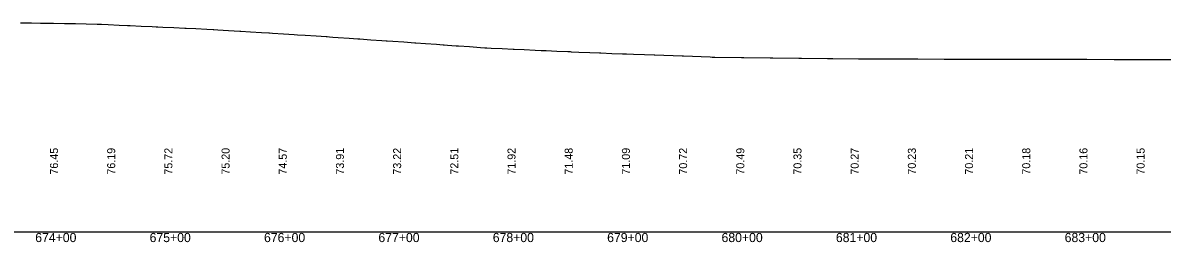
# Model space of a CAD drawing. Extents: x 2526761 to 2530854, y 882903 to 888012.
# Drawn here: x 2527707 to 2528703, y 887503 to 887695 of the extents above; entities that cross this region are included whole.
import ezdxf

# ---------------------------------------------------------------- set-up
doc = ezdxf.new("R2010")
doc.units = 0
for name, color, linetype in [('RD_DDB_Profile_EX', 7, 'Continuous'), ('RD_DDB_StaTX', 7, 'Continuous'), ('RD_DDB_StripGrade', 7, 'Continuous'), ('RD_GPK_Profile_Cell', 7, 'Continuous')]:
    doc.layers.add(name, color=color, linetype=linetype)

msp = doc.modelspace()

# ---------------------------------------------------------------- linework, layer by layer
at = {"layer": 'RD_DDB_Profile_EX'}
for points in [[(2527705.29, 887694.86), (2527714.86, 887694.71), (2527722.73, 887694.58), (2527724.43, 887694.55), (2527725.38, 887694.54), (2527734, 887694.4), (2527743.57, 887694.25), (2527747.73, 887694.18), (2527750.13, 887694.14), (2527753.14, 887694.09), (2527762.71, 887693.94), (2527772.28, 887693.78), (2527772.81, 887693.77), (2527773.7, 887693.73), (2527775.94, 887693.63), (2527781.85, 887693.36), (2527791.42, 887692.91), (2527798.7, 887692.57), (2527800.55, 887692.49), (2527800.99, 887692.47), (2527810.56, 887692.02), (2527820.13, 887691.57), (2527823.7, 887691.4), (2527825.27, 887691.33), (2527829.69, 887691.12), (2527839.26, 887690.67), (2527848.83, 887690.22), (2527850.1, 887690.16), (2527858.4, 887689.76), (2527867.97, 887689.31), (2527873.7, 887689.03), (2527874.21, 887689), (2527877.54, 887688.79), (2527887.11, 887688.19), (2527896.87, 887687.58), (2527897.77, 887687.52), (2527906.25, 887686.99), (2527915.82, 887686.38), (2527922.19, 887685.98), (2527922.71, 887685.94), (2527925.39, 887685.77), (2527934.96, 887685.16), (2527944.53, 887684.56), (2527947.38, 887684.38), (2527954.1, 887683.95), (2527963.67, 887683.34), (2527972.38, 887682.78), (2527973.24, 887682.72), (2527975.42, 887682.58), (2527978.15, 887682.39), (2527982.81, 887682.07), (2527992.38, 887681.41), (2528000.13, 887680.87), (2528000.61, 887680.83), (2528001.94, 887680.74), (2528011.51, 887680.08), (2528021.08, 887679.41), (2528024.92, 887679.15), (2528025.8, 887679.08), (2528030.65, 887678.75), (2528040.22, 887678.08), (2528049.79, 887677.42), (2528050.93, 887677.33), (2528059.36, 887676.75), (2528068.93, 887676.08), (2528074.71, 887675.68), (2528075.64, 887675.62), (2528078.5, 887675.4), (2528086.06, 887674.84), (2528087.51, 887674.74), (2528088.07, 887674.7), (2528097.64, 887673.98), (2528107.21, 887673.26), (2528111, 887672.98), (2528111.31, 887672.97), (2528112.98, 887672.85), (2528116.78, 887672.68), (2528126.35, 887672.26), (2528135.92, 887671.83), (2528136.34, 887671.82), (2528136.74, 887671.8), (2528145.49, 887671.41), (2528155.06, 887670.99), (2528160.46, 887670.75), (2528161.74, 887670.69), (2528164.63, 887670.56), (2528174.19, 887670.14), (2528183.76, 887669.72), (2528185.84, 887669.62), (2528186.73, 887669.58), (2528193.33, 887669.29), (2528202.9, 887668.87), (2528211.37, 887668.5), (2528211.83, 887668.48), (2528212.47, 887668.45), (2528222.04, 887668.12), (2528231.61, 887667.78), (2528234.84, 887667.66)], [(2528234.84, 887667.66), (2528241.18, 887667.43), (2528250.75, 887667.08), (2528259.27, 887666.77), (2528259.84, 887666.75), (2528283.73, 887665.87), (2528284.85, 887665.83), (2528308.21, 887664.97), (2528309.87, 887664.92), (2528310.6, 887664.91), (2528312.29, 887664.88), (2528335.6, 887664.56), (2528337.52, 887664.54), (2528360.6, 887664.21), (2528362.76, 887664.19), (2528385.59, 887663.87), (2528387.99, 887663.84), (2528410.84, 887663.52), (2528412.76, 887663.52), (2528415.35, 887663.5), (2528437.76, 887663.43), (2528440.09, 887663.42), (2528462.76, 887663.34), (2528464.83, 887663.33), (2528487.76, 887663.26), (2528489.56, 887663.25), (2528512.76, 887663.17), (2528516.35, 887663.17), (2528516.7, 887663.16), (2528540.18, 887663.11), (2528541.7, 887663.11), (2528565.19, 887663.06), (2528566.7, 887663.05), (2528590.2, 887663), (2528591.7, 887663), (2528615.21, 887662.95), (2528616.69, 887662.94), (2528636.44, 887662.91), (2528637.49, 887662.91), (2528661.36, 887662.86), (2528662.49, 887662.86), (2528686.55, 887662.82), (2528687.48, 887662.82), (2528711.74, 887662.78)]]:
    msp.add_lwpolyline(points, dxfattribs=at)
at = {"layer": 'RD_GPK_Profile_Cell'}
msp.add_line((2526838.95, 887512.08), (2530838.95, 887512.08), dxfattribs=at)

# ---------------------------------------------------------------- texts
at = {"layer": 'RD_DDB_StaTX'}
for s, p in [('674+00', (2527718.05, 887503.08)), ('675+00', (2527818.05, 887503.08)), ('676+00', (2527918.05, 887503.08)), ('677+00', (2528018.05, 887503.08)), ('678+00', (2528118.05, 887503.08)), ('679+00', (2528218.05, 887503.08)), ('680+00', (2528318.05, 887503.08)), ('681+00', (2528418.05, 887503.08)), ('682+00', (2528518.05, 887503.08)), ('683+00', (2528618.05, 887503.08))]:
    msp.add_text(s, height=8, dxfattribs=at).set_placement(p)
at = {"layer": 'RD_DDB_StripGrade'}
for s, p in [('76.45', (2527737.95, 887562.08)), ('76.19', (2527787.95, 887562.08)), ('75.72', (2527837.95, 887562.08)), ('75.20', (2527887.95, 887562.08)), ('74.57', (2527937.95, 887562.08)), ('73.91', (2527987.95, 887562.08)), ('73.22', (2528037.95, 887562.08)), ('72.51', (2528087.95, 887562.08)), ('71.92', (2528137.95, 887562.08)), ('71.48', (2528187.95, 887562.08)), ('71.09', (2528237.95, 887562.08)), ('70.72', (2528287.95, 887562.08)), ('70.49', (2528337.95, 887562.08)), ('70.35', (2528387.95, 887562.08)), ('70.27', (2528437.95, 887562.08)), ('70.23', (2528487.95, 887562.08)), ('70.21', (2528537.95, 887562.08)), ('70.18', (2528587.95, 887562.08)), ('70.16', (2528637.95, 887562.08)), ('70.15', (2528687.95, 887562.08))]:
    msp.add_text(s, height=7, rotation=90, dxfattribs=at).set_placement(p)

doc.saveas('drawing.dxf')
